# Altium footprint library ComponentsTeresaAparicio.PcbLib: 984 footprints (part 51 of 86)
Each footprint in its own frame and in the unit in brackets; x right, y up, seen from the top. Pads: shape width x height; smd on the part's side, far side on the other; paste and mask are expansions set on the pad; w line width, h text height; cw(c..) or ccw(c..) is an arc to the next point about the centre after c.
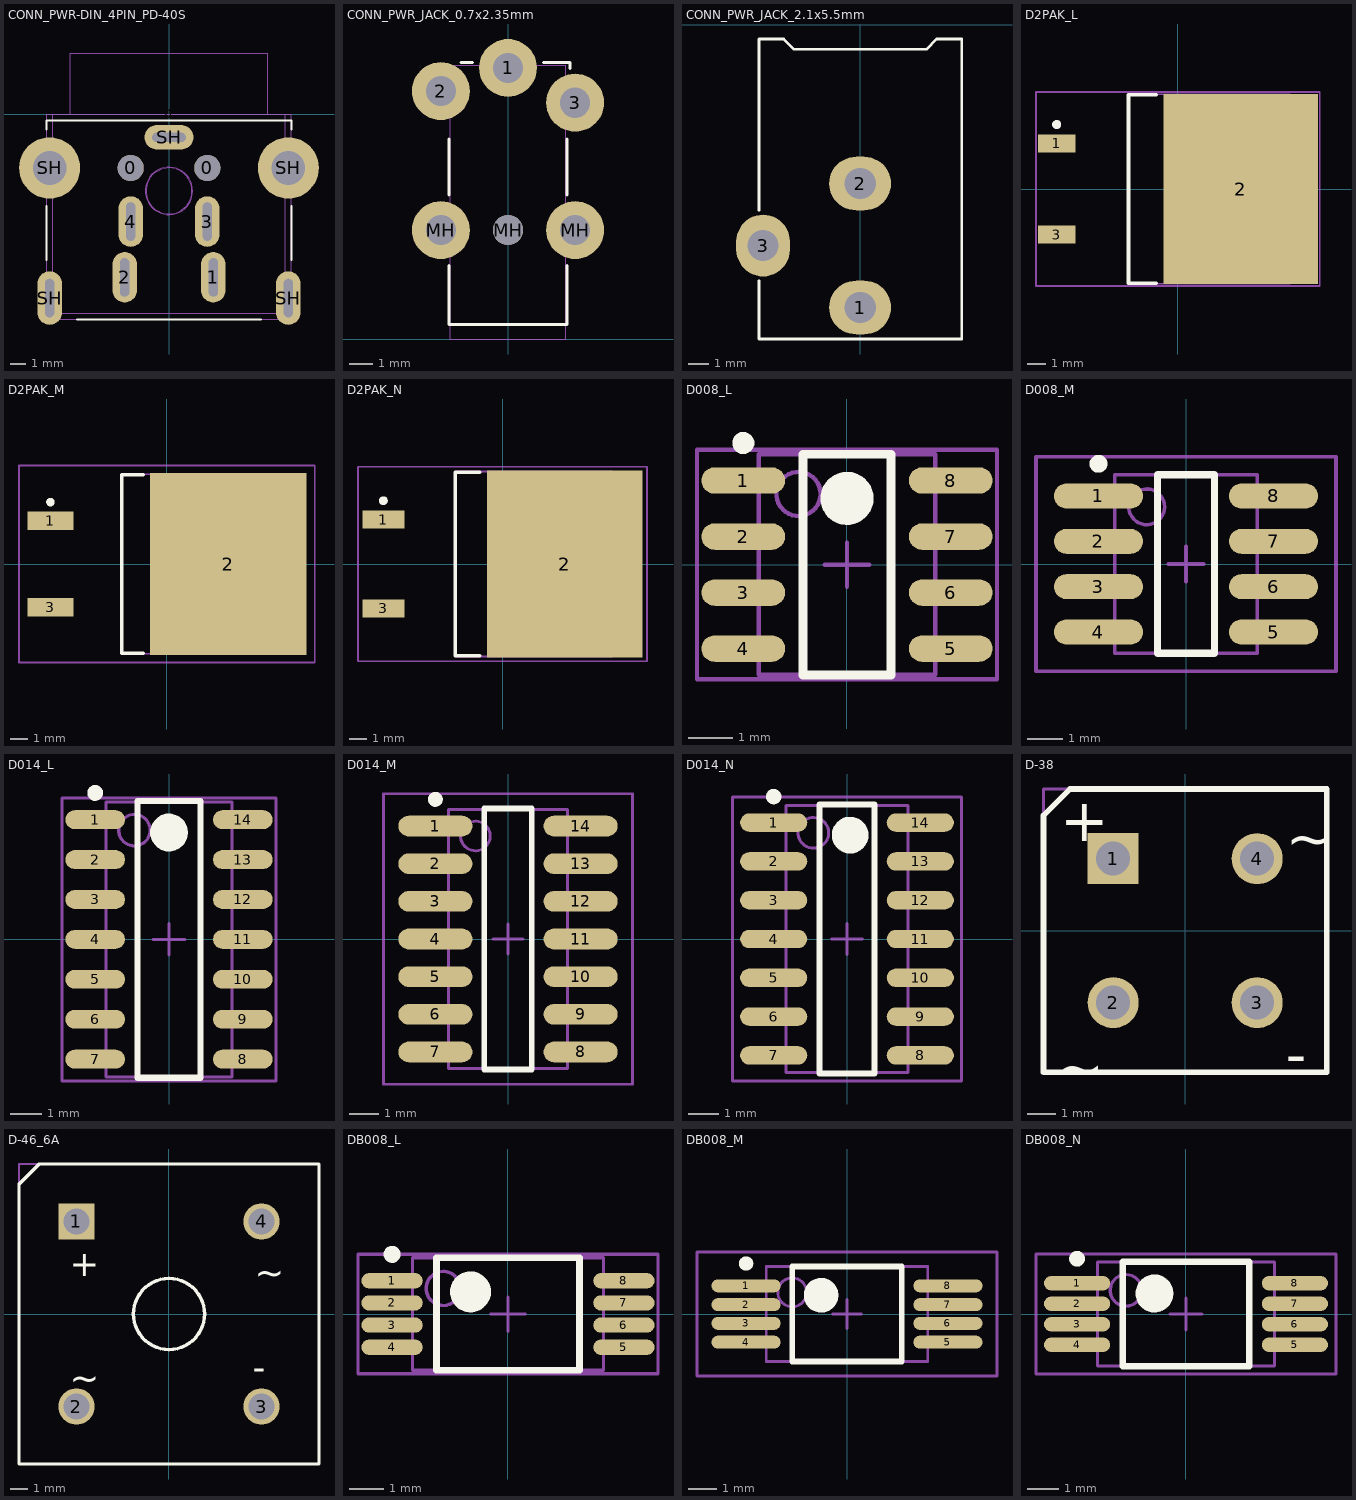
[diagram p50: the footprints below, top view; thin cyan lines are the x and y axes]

## CONN_PWR-DIN_4PIN_PD-40S [mm] "Power Connector, 4-pin DIN"
height 15
pads (12):
  round 1.7 hole 1.7 unplated: 0(-2.5,-3.5) 0(2.5,-3.5)
  round 1 on Mech14: 0(0,0)
  oval 1.6x3.3 hole 0.6 slot 2.5 at 90 deg: 1(2.9,-10.65) 2(-2.9,-10.65) 3(2.5,-7) 4(-2.5,-7)
  oval 1.6x3.5 hole 0.6 slot 2.5 at 90 deg: SH(-7.8,-12) SH(7.8,-12)
  round 4 hole 2.2: SH(-7.8,-3.5) SH(7.8,-3.5)
  oval 3.2x1.6 hole 0.6 slot 2.2 at 0 deg: SH(0,-1.5)
Top Overlay:
  lines w0.127: -8,-9.5 -8,-6 ; -8,-1 -8,-0.4 8,-0.4 8,-1 ; -6,-13.4 6,-13.4 ; 8,-9.5 8,-6
Mechanical 13:
  circle w0.05: c0,-5 r1.55
  circle w0.05: c0,-5 r1.5
  lines w0.05: -7.6,0 -7.6,-13.4 ; -6.45,0 -6.45,4 6.45,4 6.45,0 ; 7.6,0 7.6,-13.4 ; -8,-13 ccw(c-7.6,-13) -7.6,-13.4 ; -8,-13 8,-13 ; -8,-13 -8,0 8,0 8,-13 ; -7.6,-13.4 7.6,-13.4 ; 7.6,-13.4 ccw(c7.6,-13) 8,-13
3D body: height 15, standoff -3.5, extent -8,-13.4 8,4

## CONN_PWR_JACK_0.7x2.35mm [mm] "Power Connector, 0.7mm ID, 2.35mm OD"
height 5
pads (6):
  round 2.5 hole 1.3: 1(0,11.7) 2(-2.9,10.7) 3(2.9,10.2) MH(-2.9,4.7) MH(2.9,4.7)
  round 1.3 hole 1.3 unplated: MH(0,4.7)
Top Overlay:
  lines w0.127: -2.54,3.175 -2.54,0.635 2.54,0.635 2.54,3.175 ; -2.54,6.223 -2.54,8.636 ; -2.032,11.938 -1.524,11.938 ; 1.524,11.938 2.667,11.938 2.667,11.684 ; 2.54,6.223 2.54,8.636
Mechanical 13:
  lines w0.05: -2.819,4.204 -2.819,5.194 ; -2.819,10.198 -2.819,11.189 ; -2.502,4.204 -3.073,4.204 -3.073,5.194 -2.502,5.194 ; -2.502,10.198 -3.073,10.198 -3.073,11.189 -2.502,11.189 ; -0.495,11.811 -0.495,11.938 0.495,11.938 0.495,11.811 ; 2.502,4.204 3.073,4.204 3.073,5.194 2.502,5.194 ; 2.502,9.716 3.073,9.716 3.073,10.706 2.502,10.706 ; 2.819,4.204 2.819,5.194 ; 2.819,9.716 2.819,10.706 ; -2.502,0 -2.502,11.811 2.502,11.811 2.502,0 -2.502,0
3D body: height 5, standoff -2.5, extent -3.309,0 3.309,12.054

## CONN_PWR_JACK_2.1x5.5mm [mm] "Power Connector, 2.1mm ID, 5.5mm OD"
height 11
pads (3):
  oval 3x2.6 hole 1.511: 1(0,-13.7) 2(0,-7.7)
  oval 2.6x3 hole 1.511: 3(-4.7,-10.7)
Top Overlay:
  lines w0.127: -4.9,-12.4 -4.9,-15.225 4.925,-15.225 4.925,-0.7 3.7,-0.7 3.2,-1.2 -3.2,-1.2 -3.7,-0.7 -4.9,-0.7 -4.9,-9
Mechanical 13:
  lines w0.076: -4.9,-12.4 -4.9,-15.225 4.925,-15.225 4.925,-0.7 3.7,-0.7 3.2,-1.2 -3.2,-1.2 -3.7,-0.7 -4.9,-0.7 -4.9,-9
3D body: height 11, standoff -3.5, extent -4.9,-14.1 4.5,0

## D2PAK_L [mm] "D2-PAK, 4-Leads, Body 8.8x10.4mm, Pitch 2.54mm, Lead Span 15.1mm, IPC High Density"
height 4.69
pads (3):
  rect 2.1x1 smd: 1(-6.75,2.54) 3(-6.75,-2.54)
  rect 8.6x10.6 smd: 2(3.5,0)
Top Overlay:
  circle w0.25: c-6.75,3.59 r0.125
  lines w0.2: -1.2,-5.25 -2.75,-5.25 -2.75,5.25 -1.2,5.25
Mechanical 13:
  lines w0.1: -2.75,-5.275 -2.75,5.275 6.25,5.275 6.25,-5.275 -2.75,-5.275
Mechanical 15:
  lines w0.1: -0.5,0 0.5,0 ; 0,-0.5 0,0.5 ; -7.9,-5.4 -7.9,5.4 7.9,5.4 7.9,-5.4 -7.9,-5.4
3D body: height 4.69, standoff 0, extent -2.75,-5.275 6.25,5.275

## D2PAK_M [mm] "D2-PAK, 4-Leads, Body 8.8x10.4mm, Pitch 2.54mm, Lead Span 15.1mm, IPC Low Density"
height 4.69
pads (3):
  rect 2.7x1.1 smd: 1(-6.85,2.54) 3(-6.85,-2.54)
  rect 9.2x10.7 smd: 2(3.6,0)
Top Overlay:
  circle w0.25: c-6.85,3.64 r0.125
  lines w0.2: -1.4,-5.25 -2.65,-5.25 -2.65,5.25 -1.4,5.25
Mechanical 13:
  lines w0.1: -2.65,-5.275 6.35,-5.275 6.35,5.275 -2.65,5.275 -2.65,-5.275
Mechanical 15:
  lines w0.1: -0.5,0 0.5,0 ; 0,-0.5 0,0.5 ; -8.7,-5.8 8.7,-5.8 8.7,5.8 -8.7,5.8 -8.7,-5.8
3D body: height 4.69, standoff 0, extent -2.65,-5.275 6.35,5.275

## D2PAK_N [mm] "D2-PAK, 4-Leads, Body 8.8x10.4mm, Pitch 2.54mm, Lead Span 15.1mm, IPC Medium Density"
height 4.69
pads (3):
  rect 2.4x1.05 smd: 1(-6.8,2.54) 3(-6.8,-2.54)
  rect 8.9x10.65 smd: 2(3.55,0)
Top Overlay:
  circle w0.25: c-6.8,3.615 r0.125
  lines w0.2: -1.3,-5.25 -2.7,-5.25 -2.7,5.25 -1.3,5.25
Mechanical 13:
  lines w0.1: -2.7,-5.275 -2.7,5.275 6.3,5.275 6.3,-5.275 -2.7,-5.275
Mechanical 15:
  lines w0.1: -0.5,0 0.5,0 ; 0,-0.5 0,0.5 ; -8.25,-5.55 -8.25,5.55 8.25,5.55 8.25,-5.55 -8.25,-5.55
3D body: height 4.69, standoff 0, extent -2.7,-5.275 6.3,5.275

## D008_L [mm] "SOIC, 8-Leads, Body 4.9x3.9mm, Pitch 1.27mm, IPC High Density"
height 1.75
pads (8):
  oval 1.9x0.6 smd: 1(-2.35,1.905) 2(-2.35,0.635) 3(-2.35,-0.635) 4(-2.35,-1.905) 5(2.35,-1.905) 6(2.35,-0.635) 7(2.35,0.635) 8(2.35,1.905)
Top Overlay:
  circle w0.6: c0,1.5 r0.3
  circle w0.25: c-2.35,2.755 r0.125
  lines w0.2: -1,-2.5 1,-2.5 1,2.5 -1,2.5 -1,-2.5
Mechanical 13:
  circle w0.1: c-1.1,1.6 r0.5
  lines w0.1: -2,-2.5 2,-2.5 2,2.5 -2,2.5 -2,-2.5
Mechanical 15:
  lines w0.1: -0.5,0 0.5,0 ; 0,-0.5 0,0.5 ; -3.4,-2.6 3.4,-2.6 3.4,2.6 -3.4,2.6 -3.4,-2.6
3D body: height 1.75, standoff 0, extent -2,-2.5 2,2.5

## D008_M [mm] "SOIC, 8-Leads, Body 4.9x3.9mm, Pitch 1.27mm, IPC Low Density"
height 1.75
pads (8):
  oval 2.5x0.7 smd: 1(-2.45,1.905) 2(-2.45,0.635) 3(-2.45,-0.635) 4(-2.45,-1.905) 5(2.45,-1.905) 6(2.45,-0.635) 7(2.45,0.635) 8(2.45,1.905)
Top Overlay:
  circle w0.25: c-2.45,2.805 r0.125
  lines w0.2: -0.8,-2.5 -0.8,2.5 0.8,2.5 0.8,-2.5 -0.8,-2.5
Mechanical 13:
  circle w0.1: c-1.1,1.6 r0.5
  lines w0.1: -2,-2.5 -2,2.5 2,2.5 2,-2.5 -2,-2.5
Mechanical 15:
  lines w0.1: -0.5,0 0.5,0 ; 0,-0.5 0,0.5 ; -4.2,-3 -4.2,3 4.2,3 4.2,-3 -4.2,-3
3D body: height 1.75, standoff 0, extent -2,-2.5 2,2.5

## D014_L [mm] "SOIC, 14-Leads, Body 8.7x3.9mm, Pitch 1.27mm, IPC High Density"
height 1.75
pads (14):
  oval 1.9x0.6 smd: 1(-2.35,3.81) 2(-2.35,2.54) 3(-2.35,1.27) 4(-2.35,0) 5(-2.35,-1.27) 6(-2.35,-2.54) 7(-2.35,-3.81) 8(2.35,-3.81) 9(2.35,-2.54) 10(2.35,-1.27) 11(2.35,0) 12(2.35,1.27) 13(2.35,2.54) 14(2.35,3.81)
Top Overlay:
  circle w0.6: c0,3.4 r0.3
  circle w0.25: c-2.35,4.66 r0.125
  lines w0.2: -1,-4.4 1,-4.4 1,4.4 -1,4.4 -1,-4.4
Mechanical 13:
  circle w0.1: c-1.1,3.475 r0.5
  lines w0.1: -2,-4.375 2,-4.375 2,4.375 -2,4.375 -2,-4.375
Mechanical 15:
  lines w0.1: -0.5,0 0.5,0 ; 0,-0.5 0,0.5 ; -3.4,-4.5 3.4,-4.5 3.4,4.5 -3.4,4.5 -3.4,-4.5
3D body: height 1.75, standoff 0, extent -2,-4.375 2,4.375

## D014_M [mm] "SOIC, 14-Leads, Body 8.7x3.9mm, Pitch 1.27mm, IPC Low Density"
height 1.75
pads (14):
  oval 2.5x0.7 smd: 1(-2.45,3.81) 2(-2.45,2.54) 3(-2.45,1.27) 4(-2.45,0) 5(-2.45,-1.27) 6(-2.45,-2.54) 7(-2.45,-3.81) 8(2.45,-3.81) 9(2.45,-2.54) 10(2.45,-1.27) 11(2.45,0) 12(2.45,1.27) 13(2.45,2.54) 14(2.45,3.81)
Top Overlay:
  circle w0.25: c-2.45,4.71 r0.125
  lines w0.2: -0.8,-4.4 0.8,-4.4 0.8,4.4 -0.8,4.4 -0.8,-4.4
Mechanical 13:
  circle w0.1: c-1.1,3.475 r0.5
  lines w0.1: -2,-4.375 2,-4.375 2,4.375 -2,4.375 -2,-4.375
Mechanical 15:
  lines w0.1: -0.5,0 0.5,0 ; 0,-0.5 0,0.5 ; -4.2,-4.9 4.2,-4.9 4.2,4.9 -4.2,4.9 -4.2,-4.9
3D body: height 1.75, standoff 0, extent -2,-4.375 2,4.375

## D014_N [mm] "SOIC, 14-Leads, Body 8.7x3.9mm, Pitch 1.27mm, IPC Medium Density"
height 1.75
pads (14):
  oval 2.2x0.6 smd: 1(-2.4,3.81) 2(-2.4,2.54) 3(-2.4,1.27) 4(-2.4,0) 5(-2.4,-1.27) 6(-2.4,-2.54) 7(-2.4,-3.81) 8(2.4,-3.81) 9(2.4,-2.54) 10(2.4,-1.27) 11(2.4,0) 12(2.4,1.27) 13(2.4,2.54) 14(2.4,3.81)
Top Overlay:
  circle w0.25: c-2.4,4.66 r0.125
  circle w0.6: c0.1,3.4 r0.3
  lines w0.2: -0.9,-4.4 -0.9,4.4 0.9,4.4 0.9,-4.4 -0.9,-4.4
Mechanical 13:
  circle w0.1: c-1.1,3.475 r0.5
  lines w0.1: -2,-4.375 -2,4.375 2,4.375 2,-4.375 -2,-4.375
Mechanical 15:
  lines w0.1: -0.5,0 0.5,0 ; 0,-0.5 0,0.5 ; -3.75,-4.65 -3.75,4.65 3.75,4.65 3.75,-4.65 -3.75,-4.65
3D body: height 1.75, standoff 0, extent -2,-4.375 2,4.375

## D-38 [mm] "Bridge Rectifier; 4 Terminals; Body 9.4 x 9.4 mm (typ); Pitch 5.08 mm"
height 9.91
pads (4):
  rect 1.8x1.8 hole 1.2: 1(-2.54,2.54)
  round 1.8 hole 1.2: 2(-2.54,-2.54) 3(2.54,-2.54) 4(2.54,2.54)
Top Overlay:
  lines w0.2: -5,-5 -5,4.064 -4.064,5 5,5 5,-5 -5,-5
  text "+" at -4.41,3.164 h1.5
  text "-" at 3.556,-5.08 h1.5
  text "~" at -4.572,-5.588 h1.5
  text "~" at 3.556,2.54 h1.5
Mechanical 13:
  lines w0.1: -5,-5 -5,5 5,5 5,-5 -5,-5
3D body: height 9.91, standoff 0, extent -5,-5 5,5

## D-46_6A [mm] "Bridge Rectifier; 4 Terminals; Body 16.8 x 16.8 mm (typ); Pitch 10.67 mm"
height 6.35
pads (4):
  rect 2.1x2.1 hole 1.5: 1(-5.335,5.335)
  round 2.1 hole 1.5: 2(-5.335,-5.335) 3(5.335,-5.335) 4(5.335,5.335)
Top Overlay:
  circle w0.2: c0,0 r2.05
  lines w0.2: -8.65,-8.65 -8.65,7.474 -7.474,8.65 8.65,8.65 8.65,-8.65 -8.65,-8.65
  text "+" at -5.723,2.167 h1.5
  text "-" at 4.825,-3.809 h1.5
  text "~" at 4.945,1.659 h1.5
  text "~" at -5.723,-4.437 h1.5
Mechanical 13:
  lines w0.1: -8.65,-8.65 8.65,-8.65 8.65,8.65 -8.65,8.65 -8.65,-8.65
3D body: height 6.35, standoff 0, extent -8.65,-8.65 8.65,8.65

## DB008_L [mm] "SOP, 8-Leads, Body 3x5.3mm, Pitch 0.65mm, IPC High Density"
height 2
pads (8):
  oval 1.8x0.45 smd: 1(-3.4,0.975) 2(-3.4,0.325) 3(-3.4,-0.325) 4(-3.4,-0.975) 5(3.4,-0.975) 6(3.4,-0.325) 7(3.4,0.325) 8(3.4,0.975)
Top Overlay:
  circle w0.6: c-1.1,0.65 r0.3
  circle w0.25: c-3.4,1.75 r0.125
  lines w0.2: -2.1,-1.65 2.1,-1.65 2.1,1.65 -2.1,1.65 -2.1,-1.65
Mechanical 13:
  circle w0.1: c-1.9,0.75 r0.5
  lines w0.1: -2.8,-1.65 2.8,-1.65 2.8,1.65 -2.8,1.65 -2.8,-1.65
Mechanical 15:
  lines w0.1: -0.5,0 0.5,0 ; 0,-0.5 0,0.5 ; -4.4,-1.75 4.4,-1.75 4.4,1.75 -4.4,1.75 -4.4,-1.75
3D body: height 2, standoff 0, extent -2.8,-1.65 2.8,1.65

## DB008_M [mm] "SOP, 8-Leads, Body 3x5.3mm, Pitch 0.65mm, IPC Low Density"
height 2
pads (8):
  oval 2.4x0.45 smd: 1(-3.5,0.975) 2(-3.5,0.325) 3(-3.5,-0.325) 4(-3.5,-0.975) 5(3.5,-0.975) 6(3.5,-0.325) 7(3.5,0.325) 8(3.5,0.975)
Top Overlay:
  circle w0.25: c-3.5,1.75 r0.125
  circle w0.6: c-0.9,0.65 r0.3
  lines w0.2: -1.9,-1.65 -1.9,1.65 1.9,1.65 1.9,-1.65 -1.9,-1.65
Mechanical 13:
  circle w0.1: c-1.9,0.75 r0.5
  lines w0.1: -2.8,-1.65 -2.8,1.65 2.8,1.65 2.8,-1.65 -2.8,-1.65
Mechanical 15:
  lines w0.1: -0.5,0 0.5,0 ; 0,-0.5 0,0.5 ; -5.2,-2.15 -5.2,2.15 5.2,2.15 5.2,-2.15 -5.2,-2.15
3D body: height 2, standoff 0, extent -2.8,-1.65 2.8,1.65

## DB008_N [mm] "SOP, 8-Leads, Body 3x5.3mm, Pitch 0.65mm, IPC Medium Density"
height 2
pads (8):
  oval 2.1x0.45 smd: 1(-3.45,0.975) 2(-3.45,0.325) 3(-3.45,-0.325) 4(-3.45,-0.975) 5(3.45,-0.975) 6(3.45,-0.325) 7(3.45,0.325) 8(3.45,0.975)
Top Overlay:
  circle w0.6: c-1,0.65 r0.3
  circle w0.25: c-3.45,1.75 r0.125
  lines w0.2: -2,-1.65 2,-1.65 2,1.65 -2,1.65 -2,-1.65
Mechanical 13:
  circle w0.1: c-1.9,0.75 r0.5
  lines w0.1: -2.8,-1.65 2.8,-1.65 2.8,1.65 -2.8,1.65 -2.8,-1.65
Mechanical 15:
  lines w0.1: -0.5,0 0.5,0 ; 0,-0.5 0,0.5 ; -4.75,-1.9 4.75,-1.9 4.75,1.9 -4.75,1.9 -4.75,-1.9
3D body: height 2, standoff 0, extent -2.8,-1.65 2.8,1.65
